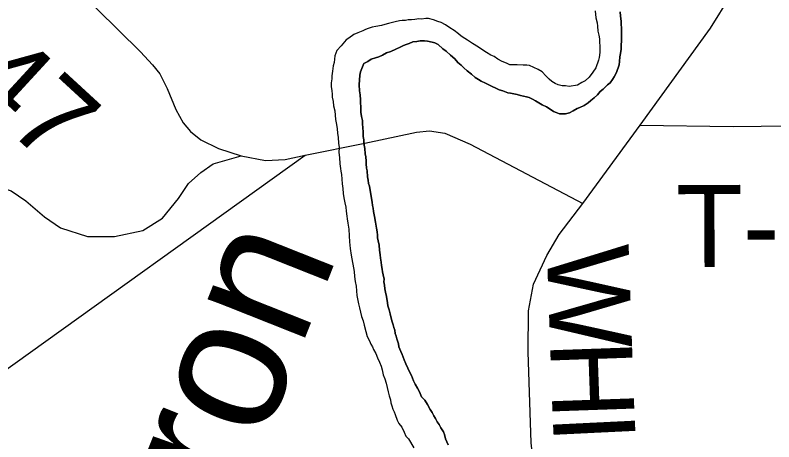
# Model space of a CAD drawing. Extents: x 0 to 34, y 0 to 22.
# Drawn here: x 22.862 to 23.388, y 14.432 to 14.728 of the extents above; entities that cross this region are included whole.
import ezdxf

# ---------------------------------------------------------------- set-up
doc = ezdxf.new("R2010")
doc.units = 0
for name, color, linetype in [('GM_X_County_Road', 7, 'Continuous'), ('GM_X_County_Road_Text', 7, 'Continuous'), ('GM_X_Major_River', 7, 'Continuous'), ('GM_X_Major_River_Text', 7, 'Continuous'), ('GM_X_Township_Road', 7, 'Continuous'), ('GM_X_Township_Road_Text', 7, 'Continuous')]:
    doc.layers.add(name, color=color, linetype=linetype)

msp = doc.modelspace()

# ---------------------------------------------------------------- linework, layer by layer
at = {"layer": 'GM_X_County_Road'}
msp.add_line((23.25552, 14.59705), (23.29547, 14.65133), dxfattribs=at)
for points in [[(23.29547, 14.65133), (23.34411, 14.71877), (23.37239, 14.76436), (23.66355, 15.1619), (23.74985, 15.27911), (23.77847, 15.32279), (23.80957, 15.36533)], [(22.83444, 14.81002), (22.87168, 14.77597), (22.91841, 14.73221), (22.94882, 14.70222), (22.95714, 14.69338), (22.96217, 14.68702), (22.96731, 14.67695), (22.97337, 14.66236), (22.9784, 14.65312), (22.98354, 14.64695), (22.99073, 14.6412), (23.00285, 14.63514), (23.01867, 14.63011), (23.03552, 14.62692), (23.04918, 14.62754), (23.06305, 14.63052)], [(23.06305, 14.63052), (23.10434, 14.63905), (23.14029, 14.64665), (23.14933, 14.64747), (23.16001, 14.64582), (23.17748, 14.63822), (23.25552, 14.59705)], [(23.3701, 14.1), (23.321, 14.19198), (23.28143, 14.26391), (23.26801, 14.29238), (23.23766, 14.36511), (23.23202, 14.38179), (23.22403, 14.40905), (23.22074, 14.42292), (23.2198, 14.43114), (23.21769, 14.49412), (23.21792, 14.52255), (23.22145, 14.54112), (23.23061, 14.56109), (23.23931, 14.57566), (23.25552, 14.59705)]]:
    msp.add_lwpolyline(points, dxfattribs=at)
at = {"layer": 'GM_X_Major_River'}
for points in [[(23.26407, 14.73074), (23.26475, 14.72579), (23.26546, 14.72236), (23.2658, 14.72008), (23.26612, 14.71665), (23.26684, 14.71398), (23.26718, 14.71132), (23.26714, 14.70866), (23.26749, 14.70676), (23.26744, 14.70372), (23.26741, 14.70182), (23.26698, 14.69841), (23.26657, 14.69651), (23.26459, 14.69123), (23.26265, 14.68822), (23.25994, 14.68484), (23.25724, 14.68223), (23.25495, 14.68112), (23.25188, 14.67927)], [(23.26407, 14.73074), (23.26475, 14.72579), (23.26546, 14.72236), (23.2658, 14.72008), (23.26612, 14.71665), (23.26684, 14.71398), (23.26718, 14.71132), (23.26714, 14.70866), (23.26749, 14.70676), (23.26744, 14.70372), (23.26741, 14.70182), (23.26698, 14.69841), (23.26657, 14.69651), (23.26459, 14.69123), (23.26265, 14.68822), (23.25994, 14.68484), (23.25724, 14.68223), (23.25495, 14.68112), (23.25188, 14.67927)], [(23.25188, 14.67927), (23.24617, 14.67822), (23.24353, 14.67865), (23.24125, 14.67868), (23.2386, 14.67948), (23.23634, 14.68028), (23.23409, 14.68183), (23.23221, 14.68338), (23.22997, 14.6857), (23.22736, 14.6884), (23.22472, 14.68996), (23.22171, 14.69153), (23.21869, 14.69272), (23.2168, 14.69312), (23.21415, 14.69317), (23.20997, 14.69323), (23.20732, 14.69328), (23.20504, 14.69331), (23.20278, 14.69449), (23.19976, 14.69568), (23.19675, 14.69724), (23.19413, 14.69918), (23.19186, 14.69998), (23.18886, 14.70193), (23.18622, 14.70349), (23.18322, 14.70544), (23.17909, 14.70816), (23.17571, 14.71049), (23.17383, 14.71166), (23.1712, 14.71322), (23.16932, 14.71477), (23.16632, 14.7171), (23.16332, 14.71904), (23.16031, 14.72099), (23.1573, 14.72256), (23.15503, 14.72336), (23.15201, 14.72454), (23.14861, 14.72536), (23.14671, 14.72539), (23.14367, 14.72506), (23.14178, 14.72509), (23.13912, 14.72475), (23.13683, 14.7244), (23.13456, 14.72444), (23.13265, 14.72409), (23.13038, 14.72413), (23.12847, 14.72378), (23.12543, 14.72307), (23.12352, 14.72272), (23.12086, 14.722), (23.11819, 14.72128), (23.1159, 14.72056), (23.11209, 14.71986), (23.10943, 14.71952), (23.10676, 14.71843), (23.10485, 14.71769), (23.10294, 14.71697), (23.0995, 14.7155), (23.09683, 14.7144), (23.09337, 14.7118), (23.09146, 14.71069), (23.08798, 14.70657), (23.08489, 14.7032), (23.08369, 14.69942), (23.08324, 14.69486), (23.08245, 14.6926), (23.08201, 14.68881), (23.08158, 14.68577), (23.08155, 14.6835), (23.08113, 14.68084), (23.08109, 14.67819), (23.08142, 14.67514), (23.08176, 14.67286), (23.08173, 14.67096), (23.08245, 14.66791), (23.08278, 14.66486), (23.08348, 14.66143), (23.08382, 14.65839), (23.08415, 14.65534), (23.08485, 14.65191), (23.08519, 14.64887), (23.08552, 14.64583), (23.08585, 14.64278), (23.08617, 14.63898), (23.0865, 14.63593), (23.08645, 14.63251), (23.08678, 14.62909), (23.08709, 14.62453), (23.08742, 14.62148), (23.08777, 14.61958), (23.08811, 14.61729), (23.08844, 14.61387), (23.08877, 14.61083), (23.0891, 14.6074), (23.08942, 14.60398), (23.08976, 14.60093), (23.09046, 14.5975), (23.09117, 14.59445), (23.09151, 14.59179), (23.09184, 14.58836), (23.09219, 14.58646)], [(23.25188, 14.67927), (23.24617, 14.67822), (23.24353, 14.67865), (23.24125, 14.67868), (23.2386, 14.67948), (23.23634, 14.68028), (23.23409, 14.68183), (23.23221, 14.68338), (23.22997, 14.6857), (23.22736, 14.6884), (23.22472, 14.68996), (23.22171, 14.69153), (23.21869, 14.69272), (23.2168, 14.69312), (23.21415, 14.69317), (23.20997, 14.69323), (23.20732, 14.69328), (23.20504, 14.69331), (23.20278, 14.69449), (23.19976, 14.69568), (23.19675, 14.69724), (23.19413, 14.69918), (23.19186, 14.69998), (23.18886, 14.70193), (23.18622, 14.70349), (23.18322, 14.70544), (23.17909, 14.70816), (23.17571, 14.71049), (23.17383, 14.71166), (23.1712, 14.71322), (23.16932, 14.71477), (23.16632, 14.7171), (23.16332, 14.71904), (23.16031, 14.72099), (23.1573, 14.72256), (23.15503, 14.72336), (23.15201, 14.72454), (23.14861, 14.72536), (23.14671, 14.72539), (23.14367, 14.72506), (23.14178, 14.72509), (23.13912, 14.72475), (23.13683, 14.7244), (23.13456, 14.72444), (23.13265, 14.72409), (23.13038, 14.72413), (23.12847, 14.72378), (23.12543, 14.72307), (23.12352, 14.72272), (23.12086, 14.722), (23.11819, 14.72128), (23.1159, 14.72056), (23.11209, 14.71986), (23.10943, 14.71952), (23.10676, 14.71843), (23.10485, 14.71769), (23.10294, 14.71697), (23.0995, 14.7155), (23.09683, 14.7144), (23.09337, 14.7118), (23.09146, 14.71069), (23.08798, 14.70657), (23.08489, 14.7032), (23.08369, 14.69942), (23.08324, 14.69486), (23.08245, 14.6926), (23.08201, 14.68881), (23.08158, 14.68577), (23.08155, 14.6835), (23.08113, 14.68084), (23.08109, 14.67819), (23.08142, 14.67514), (23.08176, 14.67286), (23.08173, 14.67096), (23.08245, 14.66791), (23.08278, 14.66486), (23.08348, 14.66143), (23.08382, 14.65839), (23.08415, 14.65534), (23.08485, 14.65191), (23.08519, 14.64887), (23.08552, 14.64583), (23.08585, 14.64278), (23.08617, 14.63898), (23.0865, 14.63593), (23.08645, 14.63251), (23.08678, 14.62909), (23.08709, 14.62453), (23.08742, 14.62148), (23.08777, 14.61958), (23.08811, 14.61729), (23.08844, 14.61387), (23.08877, 14.61083), (23.0891, 14.6074), (23.08942, 14.60398), (23.08976, 14.60093), (23.09046, 14.5975), (23.09117, 14.59445), (23.09151, 14.59179), (23.09184, 14.58836), (23.09219, 14.58646)], [(23.10269, 14.65201), (23.10273, 14.65467), (23.10202, 14.65734), (23.10168, 14.66039), (23.10171, 14.66228), (23.10174, 14.66418), (23.1014, 14.66685), (23.10144, 14.66912), (23.10111, 14.67255), (23.10078, 14.67521), (23.10046, 14.6794), (23.10095, 14.68623), (23.10136, 14.6885), (23.10373, 14.69416), (23.10641, 14.69564), (23.10871, 14.69712), (23.11176, 14.69821), (23.11405, 14.69894), (23.11672, 14.70003), (23.1194, 14.70151), (23.12245, 14.7026), (23.12589, 14.70407), (23.12895, 14.70554), (23.13124, 14.70664), (23.13315, 14.70737), (23.13506, 14.7081), (23.13774, 14.70919), (23.1404, 14.70953), (23.14268, 14.70988), (23.14571, 14.70983), (23.14799, 14.70979), (23.15101, 14.70899), (23.15291, 14.70858), (23.15517, 14.7074), (23.15853, 14.70431), (23.16078, 14.70275), (23.16378, 14.70004), (23.16677, 14.69734), (23.16902, 14.69502), (23.17126, 14.69309), (23.17313, 14.69116), (23.17538, 14.68922), (23.17838, 14.6869), (23.181, 14.68458), (23.18325, 14.68302), (23.18513, 14.68185), (23.18815, 14.68066), (23.19041, 14.67949), (23.19267, 14.67831), (23.1953, 14.67713), (23.19756, 14.67596), (23.20021, 14.67515), (23.2036, 14.67396), (23.20549, 14.67355), (23.20776, 14.67314), (23.21004, 14.67272), (23.2123, 14.67192), (23.21457, 14.67151), (23.21646, 14.6711), (23.21835, 14.67069), (23.22061, 14.66951), (23.22287, 14.66834), (23.22738, 14.66561), (23.23039, 14.66404), (23.23303, 14.66248), (23.23528, 14.66092), (23.23717, 14.66013), (23.23943, 14.65934), (23.24133, 14.65931), (23.2436, 14.65927), (23.24627, 14.65999), (23.24895, 14.66147), (23.25163, 14.66294), (23.25354, 14.66367), (23.2566, 14.66514), (23.25928, 14.667), (23.2612, 14.66849), (23.26351, 14.67035), (23.26582, 14.67259), (23.26775, 14.67484), (23.26967, 14.67633), (23.27276, 14.67932), (23.27468, 14.68081), (23.27623, 14.68306), (23.2774, 14.68495), (23.27896, 14.68796), (23.28094, 14.69325), (23.28098, 14.69552), (23.28141, 14.69894), (23.28182, 14.70121), (23.28225, 14.70424), (23.28229, 14.7069), (23.28234, 14.70994), (23.28237, 14.71184), (23.2824, 14.71412), (23.28244, 14.7164), (23.28248, 14.71905), (23.28214, 14.72134), (23.28217, 14.72362), (23.28185, 14.72704), (23.28151, 14.73008)], [(23.28151, 14.73008), (23.28185, 14.72704), (23.28217, 14.72362), (23.28214, 14.72134), (23.28248, 14.71905), (23.28244, 14.7164), (23.2824, 14.71412), (23.28237, 14.71184), (23.28234, 14.70994), (23.28229, 14.7069), (23.28225, 14.70424), (23.28182, 14.70121), (23.28141, 14.69894), (23.28098, 14.69552), (23.28094, 14.69325), (23.27896, 14.68796), (23.2774, 14.68495), (23.27623, 14.68306), (23.27468, 14.68081), (23.27276, 14.67932), (23.26967, 14.67633), (23.26775, 14.67484), (23.26582, 14.67259), (23.26351, 14.67035), (23.2612, 14.66849), (23.25928, 14.667), (23.2566, 14.66514), (23.25354, 14.66367), (23.25163, 14.66294), (23.24895, 14.66147), (23.24627, 14.65999), (23.2436, 14.65927), (23.24133, 14.65931), (23.23943, 14.65934), (23.23717, 14.66013), (23.23528, 14.66092), (23.23303, 14.66248), (23.23039, 14.66404), (23.22738, 14.66561), (23.22287, 14.66834), (23.22061, 14.66951), (23.21835, 14.67069), (23.21646, 14.6711), (23.21457, 14.67151), (23.2123, 14.67192), (23.21004, 14.67272), (23.20776, 14.67314), (23.20549, 14.67355), (23.2036, 14.67396), (23.20021, 14.67515), (23.19756, 14.67596), (23.1953, 14.67713), (23.19267, 14.67831), (23.19041, 14.67949), (23.18815, 14.68066), (23.18513, 14.68185), (23.18325, 14.68302), (23.181, 14.68458), (23.17838, 14.6869), (23.17538, 14.68922), (23.17313, 14.69116), (23.17126, 14.69309), (23.16902, 14.69502), (23.16677, 14.69734), (23.16378, 14.70004), (23.16078, 14.70275), (23.15853, 14.70431), (23.15517, 14.7074), (23.15291, 14.70858), (23.15101, 14.70899), (23.14799, 14.70979), (23.14571, 14.70983), (23.14268, 14.70988), (23.1404, 14.70953), (23.13774, 14.70919), (23.13506, 14.7081), (23.13315, 14.70737), (23.13124, 14.70664), (23.12895, 14.70554), (23.12589, 14.70407), (23.12245, 14.7026), (23.1194, 14.70151), (23.11672, 14.70003), (23.11405, 14.69894), (23.11176, 14.69821), (23.10871, 14.69712), (23.10641, 14.69564), (23.10373, 14.69416), (23.10136, 14.6885), (23.10095, 14.68623), (23.10046, 14.6794), (23.10078, 14.67521), (23.10111, 14.67255), (23.10144, 14.66912), (23.1014, 14.66685), (23.10174, 14.66418), (23.10171, 14.66228), (23.10168, 14.66039), (23.10202, 14.65734), (23.10273, 14.65467), (23.10269, 14.65201)], [(23.16224, 14.4296), (23.16041, 14.43381), (23.1597, 14.43686), (23.15897, 14.43877), (23.15711, 14.44146), (23.15601, 14.44375), (23.15452, 14.44567), (23.15342, 14.44797), (23.15231, 14.44989), (23.15121, 14.45219), (23.14972, 14.45411), (23.14788, 14.45756), (23.14603, 14.46063), (23.14378, 14.46294), (23.14232, 14.46638), (23.14084, 14.46907), (23.13937, 14.47175), (23.13826, 14.47404), (23.13681, 14.47786), (23.1357, 14.47978), (23.13423, 14.48285), (23.13276, 14.48591), (23.13166, 14.48858), (23.1302, 14.49241), (23.12947, 14.49432), (23.12801, 14.49776), (23.12766, 14.49966), (23.12657, 14.5031), (23.12622, 14.50501), (23.12549, 14.50692), (23.12515, 14.5092), (23.12442, 14.51111), (23.12407, 14.51302), (23.12334, 14.51493), (23.12262, 14.5176), (23.12191, 14.52065), (23.12119, 14.52332), (23.12047, 14.52599), (23.12013, 14.52827), (23.11943, 14.53247), (23.11872, 14.53551), (23.11838, 14.5378), (23.11804, 14.54046), (23.1177, 14.54275), (23.11773, 14.54465), (23.11701, 14.5477), (23.11667, 14.5496), (23.11632, 14.55151), (23.11598, 14.55417), (23.11563, 14.55646), (23.11529, 14.55912), (23.11495, 14.56141), (23.11462, 14.56483), (23.1143, 14.56825), (23.11359, 14.5713), (23.11324, 14.57321), (23.11327, 14.57511), (23.11292, 14.57739), (23.11258, 14.58006), (23.11189, 14.58425), (23.11119, 14.58806), (23.11048, 14.59149), (23.11014, 14.59377), (23.10979, 14.59568), (23.10944, 14.59796), (23.10911, 14.60062), (23.10772, 14.60901), (23.10699, 14.61092), (23.10664, 14.6132), (23.1063, 14.61549), (23.10599, 14.61967), (23.10564, 14.62157), (23.1053, 14.62462), (23.10533, 14.62652), (23.105, 14.62956), (23.10465, 14.63147), (23.10433, 14.63527), (23.10399, 14.63755), (23.10364, 14.63946), (23.10367, 14.64136), (23.10332, 14.64364), (23.10336, 14.6463), (23.10304, 14.65011), (23.10269, 14.65201)], [(23.10269, 14.65201), (23.10304, 14.65011), (23.10336, 14.6463), (23.10332, 14.64364), (23.10367, 14.64136), (23.10364, 14.63946), (23.10399, 14.63755), (23.10433, 14.63527), (23.10465, 14.63147), (23.105, 14.62956), (23.10533, 14.62652), (23.1053, 14.62462), (23.10564, 14.62157), (23.10599, 14.61967), (23.1063, 14.61549), (23.10664, 14.6132), (23.10699, 14.61092), (23.10772, 14.60901), (23.10911, 14.60062), (23.10944, 14.59796), (23.10979, 14.59568), (23.11014, 14.59377), (23.11048, 14.59149), (23.11119, 14.58806), (23.11189, 14.58425), (23.11258, 14.58006), (23.11292, 14.57739), (23.11327, 14.57511), (23.11324, 14.57321), (23.11359, 14.5713), (23.1143, 14.56825), (23.11462, 14.56483), (23.11495, 14.56141), (23.11529, 14.55912), (23.11563, 14.55646), (23.11598, 14.55417), (23.11632, 14.55151), (23.11667, 14.5496), (23.11701, 14.5477), (23.11773, 14.54465), (23.1177, 14.54275), (23.11804, 14.54046), (23.11838, 14.5378), (23.11872, 14.53551), (23.11943, 14.53247), (23.12013, 14.52827), (23.12047, 14.52599), (23.12119, 14.52332), (23.12191, 14.52065), (23.12262, 14.5176), (23.12334, 14.51493), (23.12407, 14.51302), (23.12442, 14.51111), (23.12515, 14.5092), (23.12549, 14.50692), (23.12622, 14.50501), (23.12657, 14.5031), (23.12766, 14.49966), (23.12801, 14.49776), (23.12947, 14.49432), (23.1302, 14.49241), (23.13166, 14.48858), (23.13276, 14.48591), (23.13423, 14.48285), (23.1357, 14.47978), (23.13681, 14.47786), (23.13826, 14.47404), (23.13937, 14.47175), (23.14084, 14.46907), (23.14232, 14.46638), (23.14378, 14.46294), (23.14603, 14.46063), (23.14788, 14.45756), (23.14972, 14.45411), (23.15121, 14.45219), (23.15231, 14.44989), (23.15342, 14.44797), (23.15452, 14.44567), (23.15601, 14.44375), (23.15711, 14.44146), (23.15897, 14.43877), (23.1597, 14.43686), (23.16041, 14.43381), (23.16224, 14.4296)], [(23.09219, 14.58646), (23.09252, 14.58341), (23.09321, 14.57922), (23.09352, 14.57466), (23.09384, 14.57048), (23.09415, 14.56592), (23.09484, 14.56135), (23.09694, 14.54992), (23.09726, 14.54649), (23.09759, 14.54307), (23.09829, 14.53964), (23.09863, 14.53659), (23.09895, 14.53317), (23.09966, 14.52974), (23.1, 14.52745), (23.10072, 14.52479), (23.10143, 14.52173), (23.10214, 14.51869), (23.10324, 14.51563), (23.10395, 14.51258), (23.10502, 14.50838), (23.1061, 14.50494), (23.10757, 14.50188), (23.10868, 14.49959), (23.10979, 14.49767), (23.11052, 14.49576), (23.11199, 14.49308), (23.11308, 14.49002), (23.11456, 14.48696), (23.11565, 14.48428), (23.11637, 14.48161), (23.11708, 14.47818), (23.11817, 14.4755), (23.11926, 14.47245), (23.11998, 14.4694), (23.12069, 14.46635), (23.1214, 14.46368), (23.12212, 14.461), (23.12247, 14.45872), (23.1232, 14.45681), (23.12392, 14.45452), (23.12465, 14.45261), (23.12538, 14.4507), (23.12684, 14.44687), (23.12794, 14.44458), (23.13018, 14.44188), (23.13164, 14.43844), (23.13274, 14.43576), (23.1346, 14.43384), (23.1383, 14.4277)], [(23.09219, 14.58646), (23.09252, 14.58341), (23.09321, 14.57922), (23.09352, 14.57466), (23.09384, 14.57048), (23.09415, 14.56592), (23.09484, 14.56135), (23.09694, 14.54992), (23.09726, 14.54649), (23.09759, 14.54307), (23.09829, 14.53964), (23.09863, 14.53659), (23.09895, 14.53317), (23.09966, 14.52974), (23.1, 14.52745), (23.10072, 14.52479), (23.10143, 14.52173), (23.10214, 14.51869), (23.10324, 14.51563), (23.10395, 14.51258), (23.10502, 14.50838), (23.1061, 14.50494), (23.10757, 14.50188), (23.10868, 14.49959), (23.10979, 14.49767), (23.11052, 14.49576), (23.11199, 14.49308), (23.11308, 14.49002), (23.11456, 14.48696), (23.11565, 14.48428), (23.11637, 14.48161), (23.11708, 14.47818), (23.11817, 14.4755), (23.11926, 14.47245), (23.11998, 14.4694), (23.12069, 14.46635), (23.1214, 14.46368), (23.12212, 14.461), (23.12247, 14.45872), (23.1232, 14.45681), (23.12392, 14.45452), (23.12465, 14.45261), (23.12538, 14.4507), (23.12684, 14.44687), (23.12794, 14.44458), (23.13018, 14.44188), (23.13164, 14.43844), (23.13274, 14.43576), (23.1346, 14.43384), (23.1383, 14.4277)]]:
    msp.add_lwpolyline(points, dxfattribs=at)
at = {"layer": 'GM_X_Township_Road'}
msp.add_line((22.8438, 14.47353), (23.06305, 14.63052), dxfattribs=at)
for points in [[(23.29547, 14.65133), (23.35983, 14.65045), (23.67216, 14.65415), (23.75888, 14.65321), (23.78097, 14.65415), (23.79483, 14.65697), (23.80564, 14.6619), (23.82303, 14.67436), (23.84324, 14.68752), (23.85452, 14.69151), (23.86386, 14.69394), (23.87379, 14.69551), (23.88366, 14.69551), (23.89658, 14.69292), (23.90246, 14.69128), (23.91374, 14.68564), (23.95439, 14.65814), (23.96473, 14.65368), (23.97766, 14.65086), (24.19029, 14.65408)], [(22.83886, 14.61537), (22.84369, 14.6109), (22.85906, 14.60578), (22.86931, 14.59895), (22.88212, 14.58784), (22.89322, 14.58016), (22.912, 14.57418), (22.9308, 14.57419), (22.95044, 14.57846), (22.9641, 14.587), (22.9752, 14.60066), (22.98203, 14.61091), (22.99057, 14.6186), (22.99911, 14.62457), (23.01867, 14.63011)]]:
    msp.add_lwpolyline(points, dxfattribs=at)

# ---------------------------------------------------------------- texts
at = {"layer": 'GM_X_County_Road_Text'}
for s, height, rotation, p in [('C-47', 0.056818, 317.4053, (22.76476, 14.73229)), ('W', 0.05682, 271.9509, (23.23058, 14.56736)), ('H', 0.05682, 272.0157, (23.23282, 14.5015)), ('I', 0.05682, 272.7758, (23.23462, 14.45071))]:
    msp.add_text(s, height=height, rotation=rotation, dxfattribs=at).set_placement(p)
at = {"layer": 'GM_X_Major_River_Text'}
msp.add_text('Huron', height=0.094753, rotation=68.3537, dxfattribs=at).set_placement((22.95845, 14.24065))
at = {"layer": 'GM_X_Township_Road_Text'}
msp.add_text('T-125', height=0.056818, rotation=0.2807, dxfattribs=at).set_placement((23.32038, 14.55301))

doc.saveas('drawing.dxf')
